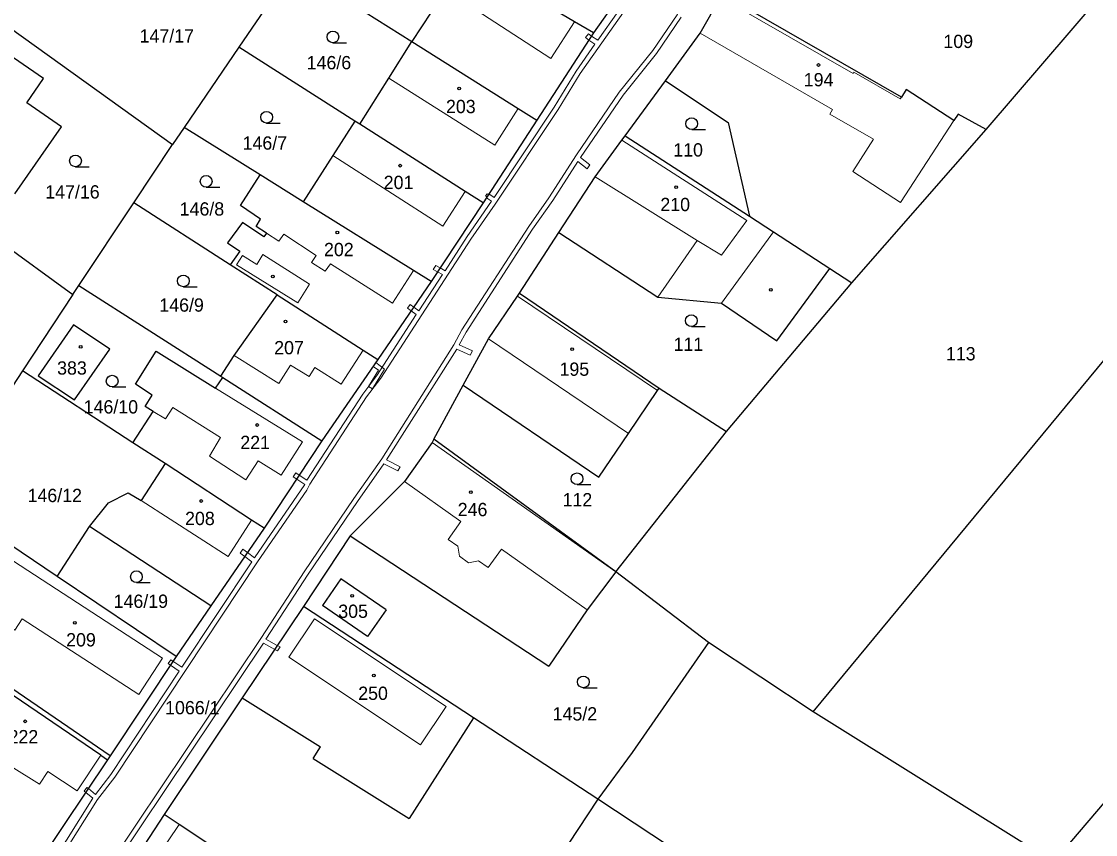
# Model space of a CAD drawing. Extents: x -694609 to -690140, y -1033292 to -1029794.
# Drawn here: x -692824.6 to -692687.4, y -1031527.4 to -1031423.4 of the extents above; entities that cross this region are included whole.
import ezdxf
from ezdxf.enums import TextEntityAlignment as Align

# ---------------------------------------------------------------- set-up
doc = ezdxf.new("R2010")
doc.units = 0
doc.header["$LTSCALE"] = 0.68
for name, color, linetype, lineweight in [('1', 7, 'Continuous', 25), ('13', 7, 'Continuous', 13), ('3', 7, 'Continuous', 25), ('4', 7, 'Continuous', 13), ('5', 7, 'Continuous', 25)]:
    doc.layers.add(name, color=color, linetype=linetype, lineweight=lineweight)
doc.layers.add('2', color=7, linetype='Continuous')

msp = doc.modelspace()

# ---------------------------------------------------------------- linework, layer by layer
at = {"layer": '1'}
for p, q in [((-692743.74, -1031413.72), (-692751.52, -1031424.89)), ((-692753.94, -1031423.46), (-692767.77, -1031415.32)), ((-692789.88, -1031416.45), (-692796.87, -1031426.72)), ((-692789.88, -1031416.45), (-692774.74, -1031425.99)), ((-692701.34, -1031437.24), (-692684.27, -1031417.34)), ((-692832.99, -1031419.3), (-692805.34, -1031439.18)), ((-692770.44, -1031419.41), (-692774.74, -1031425.99)), ((-692712.18, -1031433.11), (-692734.45, -1031420.29)), ((-692751.52, -1031424.89), (-692753.94, -1031423.46)), ((-692751.52, -1031424.89), (-692758.78, -1031436.05)), ((-692742.33, -1031431.01), (-692737.89, -1031424.94)), ((-692821.85, -1031430.74), (-692827.61, -1031426.76)), ((-692796.87, -1031426.72), (-692803.86, -1031437)), ((-692782.03, -1031436.18), (-692796.87, -1031426.72)), ((-692777.68, -1031430.66), (-692774.74, -1031425.99)), ((-692774.74, -1031425.99), (-692761.15, -1031434.55)), ((-692823.98, -1031433.82), (-692821.85, -1031430.74)), ((-692781.41, -1031436.58), (-692777.68, -1031430.66)), ((-692747.5, -1031438.07), (-692742.33, -1031431.01)), ((-692742.33, -1031431.01), (-692734.34, -1031436.36)), ((-692819.54, -1031436.89), (-692823.98, -1031433.82)), ((-692761.15, -1031434.55), (-692758.78, -1031436.05)), ((-692782.03, -1031436.18), (-692784.85, -1031440.58)), ((-692781.41, -1031436.58), (-692782.03, -1031436.18)), ((-692767.95, -1031445.16), (-692781.41, -1031436.58)), ((-692758.78, -1031436.05), (-692765.64, -1031446.63)), ((-692734.34, -1031436.36), (-692731.59, -1031448.35)), ((-692723.47, -1031511.71), (-692660.69, -1031435.82)), ((-692846.51, -1031437.82), (-692818.08, -1031458.33)), ((-692825.49, -1031445.49), (-692819.54, -1031436.89)), ((-692803.86, -1031437), (-692805.34, -1031439.18)), ((-692794.14, -1031443.05), (-692803.86, -1031437)), ((-692747.9, -1031438.62), (-692747.5, -1031438.07)), ((-692747.5, -1031438.07), (-692731.59, -1031448.35)), ((-692718.5, -1031456.87), (-692701.34, -1031437.24)), ((-692810.29, -1031446.62), (-692805.34, -1031439.18)), ((-692784.85, -1031440.58), (-692788.63, -1031446.48)), ((-692796.67, -1031446.97), (-692794.14, -1031443.05)), ((-692788.63, -1031446.48), (-692794.14, -1031443.05)), ((-692765.64, -1031446.63), (-692767.95, -1031445.16)), ((-692817.33, -1031457.2), (-692810.29, -1031446.62)), ((-692797.96, -1031454.55), (-692810.29, -1031446.62)), ((-692794.1, -1031448.71), (-692796.67, -1031446.97)), ((-692774.52, -1031455.26), (-692788.63, -1031446.48)), ((-692765.64, -1031446.63), (-692772.26, -1031456.67)), ((-692796.41, -1031449.12), (-692798.33, -1031451.74)), ((-692793.65, -1031450.98), (-692796.41, -1031449.12)), ((-692794.66, -1031449.64), (-692794.1, -1031448.71)), ((-692731.59, -1031448.35), (-692728.54, -1031450.33)), ((-692793.33, -1031450.5), (-692794.66, -1031449.64)), ((-692793.33, -1031450.5), (-692793.65, -1031450.98)), ((-692728.54, -1031450.33), (-692721.33, -1031455.03)), ((-692798.33, -1031451.74), (-692796.75, -1031452.81)), ((-692796.75, -1031452.81), (-692797.96, -1031454.55)), ((-692791.95, -1031458.41), (-692797.96, -1031454.55)), ((-692692.71, -1031530.91), (-692627.47, -1031454.27)), ((-692772.26, -1031456.67), (-692774.52, -1031455.26)), ((-692728.11, -1031464.28), (-692721.33, -1031455.03)), ((-692721.33, -1031455.03), (-692718.5, -1031456.87)), ((-692818.08, -1031458.33), (-692817.33, -1031457.2)), ((-692817.33, -1031457.2), (-692799.18, -1031468.8)), ((-692772.26, -1031456.67), (-692779.09, -1031466.68)), ((-692734.52, -1031475.87), (-692718.5, -1031456.87)), ((-692818.08, -1031458.33), (-692824.52, -1031468.13)), ((-692797.46, -1031466.14), (-692791.95, -1031458.41)), ((-692791.95, -1031458.41), (-692780.96, -1031465.48)), ((-692761.24, -1031458.54), (-692761, -1031458.16)), ((-692761, -1031458.16), (-692743.13, -1031470.31)), ((-692743.3, -1031458.68), (-692735.18, -1031459.46)), ((-692735.18, -1031459.46), (-692728.11, -1031464.28)), ((-692817.98, -1031462.22), (-692822.5, -1031468.73)), ((-692813.36, -1031465.34), (-692817.98, -1031462.22)), ((-692817.88, -1031471.82), (-692813.36, -1031465.34)), ((-692810.08, -1031469.81), (-692807.42, -1031465.59)), ((-692807.42, -1031465.59), (-692799.83, -1031470.31)), ((-692780.96, -1031465.48), (-692779.09, -1031466.68)), ((-692799.18, -1031468.8), (-692797.46, -1031466.14)), ((-692779.09, -1031466.68), (-692786.24, -1031477.07)), ((-692824.52, -1031468.13), (-692830.61, -1031477.39)), ((-692810.41, -1031477.3), (-692824.52, -1031468.13)), ((-692822.5, -1031468.73), (-692817.88, -1031471.82)), ((-692799.83, -1031470.31), (-692798.93, -1031468.96)), ((-692799.18, -1031468.8), (-692798.93, -1031468.96)), ((-692798.93, -1031468.96), (-692786.24, -1031477.07)), ((-692807.94, -1031471.2), (-692810.08, -1031469.81)), ((-692771.94, -1031476.85), (-692768.18, -1031469.96)), ((-692768.18, -1031469.96), (-692750.83, -1031481.7)), ((-692747.05, -1031476.11), (-692743.35, -1031470.64)), ((-692743.35, -1031470.64), (-692743.13, -1031470.31)), ((-692743.13, -1031470.31), (-692734.52, -1031475.87)), ((-692808.83, -1031472.66), (-692807.94, -1031471.2)), ((-692810.41, -1031477.3), (-692807.8, -1031473.29)), ((-692807.8, -1031473.29), (-692808.83, -1031472.66)), ((-692750.83, -1031481.7), (-692747.05, -1031476.11)), ((-692748.67, -1031493.81), (-692734.52, -1031475.87)), ((-692806.3, -1031479.98), (-692810.41, -1031477.3)), ((-692786.24, -1031477.07), (-692793.62, -1031488.22)), ((-692772.17, -1031477.28), (-692775.69, -1031482.26)), ((-692771.94, -1031476.85), (-692772.17, -1031477.28)), ((-692748.67, -1031493.81), (-692771.94, -1031476.85)), ((-692806.3, -1031479.98), (-692809.33, -1031484.69)), ((-692795.24, -1031487.22), (-692806.3, -1031479.98)), ((-692775.69, -1031482.26), (-692782.63, -1031489.23)), ((-692820.1, -1031494.39), (-692835.25, -1031484.19)), ((-692813.51, -1031484.98), (-692811.03, -1031483.73)), ((-692811.03, -1031483.73), (-692809.33, -1031484.69)), ((-692815.93, -1031488.02), (-692813.51, -1031484.98)), ((-692793.62, -1031488.22), (-692795.24, -1031487.22)), ((-692820.1, -1031494.39), (-692815.93, -1031488.02)), ((-692800.44, -1031498.16), (-692815.93, -1031488.02)), ((-692793.62, -1031488.22), (-692800.44, -1031498.16)), ((-692782.63, -1031489.23), (-692788.61, -1031498.23)), ((-692782.63, -1031489.23), (-692757.26, -1031505.86)), ((-692804.88, -1031504.64), (-692820.1, -1031494.39)), ((-692748.67, -1031493.81), (-692752.33, -1031498.69)), ((-692736.84, -1031502.87), (-692748.67, -1031493.81)), ((-692783.83, -1031494.7), (-692786.18, -1031498.12)), ((-692778.05, -1031498.67), (-692783.83, -1031494.7)), ((-692800.44, -1031498.16), (-692804.88, -1031504.64)), ((-692788.61, -1031498.23), (-692796.44, -1031509.94)), ((-692766.86, -1031512.47), (-692788.61, -1031498.23)), ((-692780.4, -1031502.09), (-692786.18, -1031498.12)), ((-692778.05, -1031498.67), (-692780.4, -1031502.09)), ((-692752.33, -1031498.69), (-692757.26, -1031505.86)), ((-692736.84, -1031502.87), (-692746.58, -1031516.93)), ((-692723.47, -1031511.71), (-692736.84, -1031502.87)), ((-692814.52, -1031517.26), (-692833.22, -1031504.54)), ((-692804.88, -1031504.64), (-692813.29, -1031517.36)), ((-692813.29, -1031517.36), (-692827.38, -1031507.7)), ((-692796.44, -1031509.94), (-692806.41, -1031524.86)), ((-692796.44, -1031509.94), (-692786.44, -1031516.19)), ((-692692.71, -1031530.91), (-692723.47, -1031511.71)), ((-692766.86, -1031512.47), (-692775.09, -1031525.37)), ((-692750.99, -1031522.87), (-692766.86, -1031512.47)), ((-692787.37, -1031517.68), (-692786.44, -1031516.19)), ((-692814.52, -1031517.26), (-692813.63, -1031517.87)), ((-692813.29, -1031517.36), (-692813.63, -1031517.87)), ((-692787.37, -1031517.68), (-692775.09, -1031525.37)), ((-692746.58, -1031516.93), (-692750.99, -1031522.87)), ((-692813.63, -1031517.87), (-692824.08, -1031533.37)), ((-692750.99, -1031522.87), (-692768.7, -1031549.76)), ((-692678.79, -1031570.47), (-692750.99, -1031522.87)), ((-692796.91, -1031531.13), (-692804.51, -1031526.12))]:
    msp.add_line(p, q, dxfattribs=at)
for points in [[(-692737.89, -1031424.94), (-692735.3, -1031420.32), (-692734.72, -1031420.66)], [(-692705.48, -1031436.11), (-692711.56, -1031432.15), (-692712.18, -1031433.11)], [(-692701.34, -1031437.24), (-692704.93, -1031435.27), (-692705.48, -1031436.11)], [(-692755.95, -1031450.41), (-692751.31, -1031443.28), (-692747.9, -1031438.62)], [(-692761, -1031458.16), (-692755.95, -1031450.41), (-692743.3, -1031458.68)], [(-692768.18, -1031469.96), (-692764.94, -1031464), (-692761.24, -1031458.54)], [(-692804.51, -1031526.12), (-692806.41, -1031524.86), (-692816.15, -1031539.83)]]:
    msp.add_lwpolyline(points, dxfattribs=at)
at = {"layer": '13'}
for points in [[(-692821.78, -1031533.86), (-692814.94, -1031522.92), (-692812.73, -1031520.08), (-692794.48, -1031492.55), (-692788.19, -1031483.36), (-692787.79, -1031482.62), (-692780.53, -1031471.44), (-692778.71, -1031469.03), (-692767.21, -1031451.27), (-692764.08, -1031446.79), (-692756.04, -1031434.68), (-692753.23, -1031430.1), (-692736.34, -1031406.09), (-692736.18, -1031405.56), (-692732.41, -1031400.24), (-692726.28, -1031399.91), (-692722.14, -1031396.02), (-692720.43, -1031393.92), (-692719.16, -1031392.37), (-692711.07, -1031383.61), (-692701.14, -1031373.4), (-692697.25, -1031376.64), (-692705.94, -1031386.76)], [(-692731.48, -1031411.34), (-692737.54, -1031417.26), (-692738.96, -1031419.23), (-692740.83, -1031422.56), (-692743.96, -1031427.15), (-692748.24, -1031432.48), (-692753.7, -1031440.49), (-692757.22, -1031445.99), (-692759.8, -1031449.66), (-692768.34, -1031462.88), (-692769.39, -1031464.78), (-692778.6, -1031479.36), (-692782.17, -1031484.44), (-692788.53, -1031493.82), (-692793.95, -1031502.2), (-692813.14, -1031530.87)], [(-692743.18, -1031414.8), (-692750.99, -1031425.83), (-692751.78, -1031425.29), (-692752.11, -1031425.8), (-692751.34, -1031426.33), (-692753.75, -1031429.79), (-692756.55, -1031434.37), (-692764.24, -1031445.94), (-692764.9, -1031445.48), (-692765.22, -1031445.98), (-692764.57, -1031446.43), (-692767.7, -1031450.92), (-692770.49, -1031455.3), (-692771.13, -1031454.95), (-692771.46, -1031455.46), (-692770.82, -1031455.8), (-692773.85, -1031460.44), (-692774.5, -1031459.95), (-692774.84, -1031460.45), (-692774.19, -1031460.92), (-692779.21, -1031468.7), (-692781.03, -1031471.1), (-692788.17, -1031482.1), (-692789.14, -1031481.45), (-692789.47, -1031481.95), (-692788.43, -1031482.65), (-692794.85, -1031492.03), (-692795.77, -1031491.36), (-692796.11, -1031491.85), (-692795.19, -1031492.52), (-692804.14, -1031506), (-692805.28, -1031505.25), (-692805.61, -1031505.74), (-692804.47, -1031506.5), (-692813.22, -1031519.73), (-692815.19, -1031522.27), (-692816.1, -1031521.54), (-692816.43, -1031522.03), (-692815.54, -1031522.77), (-692822.27, -1031533.51)], [(-692812.54, -1031531.06), (-692793.72, -1031502.94), (-692792.28, -1031503.73), (-692791.95, -1031503.23), (-692793.4, -1031502.44), (-692788, -1031494.11), (-692781.7, -1031484.81), (-692778.32, -1031480.01), (-692776.56, -1031480.89), (-692776.23, -1031480.37), (-692778, -1031479.51), (-692769.01, -1031465.32), (-692767.3, -1031466.09), (-692766.99, -1031465.57), (-692768.71, -1031464.8), (-692767.81, -1031463.18), (-692759.31, -1031450.01), (-692756.72, -1031446.31), (-692753.53, -1031441.32), (-692752.32, -1031442.28), (-692752, -1031441.76), (-692753.19, -1031440.82), (-692747.76, -1031432.84), (-692743.48, -1031427.51), (-692740.31, -1031422.87)]]:
    msp.add_lwpolyline(points, dxfattribs=at)
for points in [[(-692752.54, -1031425.5), (-692752.11, -1031425.8), (-692751.78, -1031425.29), (-692752.18, -1031425.01)], [(-692765.14, -1031445.47), (-692765.32, -1031445.74), (-692765.14, -1031445.86), (-692764.96, -1031445.59)], [(-692771.69, -1031454.64), (-692772.01, -1031455.16), (-692771.46, -1031455.46), (-692771.13, -1031454.95)], [(-692775.32, -1031460.09), (-692774.84, -1031460.45), (-692774.5, -1031459.95), (-692774.96, -1031459.61)], [(-692779.34, -1031467.04), (-692779.68, -1031467.54), (-692779.03, -1031468.03), (-692780.3, -1031470.12), (-692779.79, -1031470.43), (-692778.23, -1031467.89)], [(-692789.57, -1031481.16), (-692789.92, -1031481.65), (-692789.47, -1031481.95), (-692789.14, -1031481.45)], [(-692796.11, -1031491.85), (-692795.77, -1031491.36), (-692796.36, -1031490.93), (-692796.71, -1031491.42)], [(-692791.95, -1031503.23), (-692792.28, -1031503.73), (-692791.93, -1031503.92), (-692791.6, -1031503.42)], [(-692805.61, -1031505.74), (-692805.28, -1031505.25), (-692805.56, -1031505.06), (-692805.9, -1031505.54)], [(-692816.62, -1031521.88), (-692816.43, -1031522.03), (-692816.1, -1031521.54), (-692816.28, -1031521.39)]]:
    msp.add_lwpolyline(points, close=True, dxfattribs=at)
at = {"layer": '3'}
for p, q in [((-692784.843, -1031426.15), (-692783.093, -1031426.15)), ((-692793.313, -1031436.43), (-692791.563, -1031436.43)), ((-692738.983, -1031437.25), (-692737.233, -1031437.25)), ((-692817.743, -1031442.01), (-692815.993, -1031442.01)), ((-692801.043, -1031444.63), (-692799.293, -1031444.63)), ((-692803.953, -1031457.36), (-692802.203, -1031457.36)), ((-692739.023, -1031462.44), (-692737.273, -1031462.44)), ((-692813.053, -1031470.17), (-692811.303, -1031470.17)), ((-692753.633, -1031482.66), (-692751.883, -1031482.66)), ((-692809.953, -1031495.19), (-692808.203, -1031495.19)), ((-692752.833, -1031508.64), (-692751.083, -1031508.64))]:
    msp.add_line(p, q, dxfattribs=at)
for centre in [(-692784.8429, -1031425.3998), (-692793.3129, -1031435.6798), (-692738.9829, -1031436.4998), (-692817.7429, -1031441.2598), (-692801.0429, -1031443.8798), (-692803.9529, -1031456.6098), (-692739.0229, -1031461.6898), (-692813.0529, -1031469.4198), (-692753.6329, -1031481.9098), (-692809.9529, -1031494.4398), (-692752.8329, -1031507.8898)]:
    msp.add_circle(centre, 0.75, dxfattribs=at)
at = {"layer": '4'}
for p, q in [((-692770.44, -1031419.41), (-692757, -1031428.16)), ((-692753.94, -1031423.46), (-692757, -1031428.16)), ((-692737.89, -1031424.94), (-692720.99, -1031434.67)), ((-692777.68, -1031430.66), (-692764.15, -1031439.26)), ((-692761.15, -1031434.55), (-692764.15, -1031439.26)), ((-692721.34, -1031435.27), (-692720.99, -1031434.67)), ((-692715.73, -1031438.5), (-692721.34, -1031435.27)), ((-692705.48, -1031436.11), (-692712.31, -1031446.58)), ((-692747.9, -1031438.62), (-692731.94, -1031448.89)), ((-692718.38, -1031442.62), (-692715.73, -1031438.5)), ((-692784.85, -1031440.58), (-692770.79, -1031449.59)), ((-692751.31, -1031443.28), (-692738.26, -1031451.44)), ((-692718.38, -1031442.62), (-692712.31, -1031446.58)), ((-692767.95, -1031445.16), (-692770.79, -1031449.59)), ((-692731.94, -1031448.89), (-692735.19, -1031453.32)), ((-692791.73, -1031451.54), (-692793.33, -1031450.5)), ((-692735.18, -1031459.46), (-692728.54, -1031450.33)), ((-692791.13, -1031450.62), (-692791.73, -1031451.54)), ((-692786.96, -1031453.35), (-692791.13, -1031450.62)), ((-692793.81, -1031453.25), (-692794.56, -1031454.51)), ((-692787.82, -1031457.04), (-692793.81, -1031453.25)), ((-692796.4, -1031453.34), (-692797.18, -1031454.54)), ((-692797.18, -1031454.54), (-692789.32, -1031459.4)), ((-692794.56, -1031454.51), (-692796.4, -1031453.34)), ((-692787.57, -1031454.27), (-692786.96, -1031453.35)), ((-692785.82, -1031455.36), (-692787.57, -1031454.27)), ((-692785.16, -1031454.41), (-692785.82, -1031455.36)), ((-692777.22, -1031459.45), (-692785.16, -1031454.41)), ((-692774.52, -1031455.26), (-692777.22, -1031459.45)), ((-692789.32, -1031459.4), (-692787.82, -1031457.04)), ((-692761.24, -1031458.54), (-692743.35, -1031470.64)), ((-692764.94, -1031464), (-692747.05, -1031476.11)), ((-692790.26, -1031467.37), (-692787.87, -1031468.84)), ((-692787.87, -1031468.84), (-692787.16, -1031467.7)), ((-692799.83, -1031470.31), (-692788.72, -1031477.21)), ((-692807.8, -1031473.29), (-692806.22, -1031474.26)), ((-692805.31, -1031472.79), (-692806.22, -1031474.26)), ((-692799.19, -1031476.64), (-692805.31, -1031472.79)), ((-692800.62, -1031479.01), (-692799.19, -1031476.64)), ((-692788.72, -1031477.21), (-692791.45, -1031481.46)), ((-692748.67, -1031493.81), (-692772.17, -1031477.28)), ((-692795.95, -1031482.03), (-692800.62, -1031479.01)), ((-692794.38, -1031479.64), (-692795.95, -1031482.03)), ((-692791.45, -1031481.46), (-692794.38, -1031479.64)), ((-692809.33, -1031484.69), (-692798.21, -1031491.84)), ((-692795.24, -1031487.22), (-692798.21, -1031491.84)), ((-692825.66, -1031492.47), (-692806.62, -1031504.84)), ((-692787.18, -1031499.81), (-692790.46, -1031504.72)), ((-692770.38, -1031511.03), (-692787.18, -1031499.81)), ((-692806.62, -1031504.84), (-692809.66, -1031509.52)), ((-692773.66, -1031515.94), (-692790.46, -1031504.72)), ((-692770.38, -1031511.03), (-692773.66, -1031515.94)), ((-692814.52, -1031517.26), (-692817.53, -1031521.82)), ((-692825.95, -1031518.71), (-692822.35, -1031520.99)), ((-692822.35, -1031520.99), (-692821.27, -1031519.35)), ((-692821.27, -1031519.35), (-692817.53, -1031521.82)), ((-692804.51, -1031526.12), (-692811.49, -1031536.48))]:
    msp.add_line(p, q, dxfattribs=at)
for points in [[(-692734.72, -1031420.66), (-692718.36, -1031430.08), (-692718.26, -1031429.9), (-692712.32, -1031433.32), (-692712.18, -1031433.11)], [(-692743.3, -1031458.68), (-692738.26, -1031451.44), (-692735.19, -1031453.32)], [(-692787.16, -1031467.7), (-692783.79, -1031469.83), (-692780.96, -1031465.48)], [(-692797.46, -1031466.14), (-692791.75, -1031469.72), (-692790.26, -1031467.37)], [(-692775.69, -1031482.26), (-692768.47, -1031487.36), (-692770.11, -1031489.67), (-692768.88, -1031490.53), (-692768.65, -1031491.8), (-692767.49, -1031492.65), (-692766.21, -1031492.42), (-692764.99, -1031493.27), (-692763.3, -1031490.93), (-692752.33, -1031498.69)], [(-692829.67, -1031498.53), (-692825.5, -1031501.29), (-692824.56, -1031499.84), (-692809.66, -1031509.52)]]:
    msp.add_lwpolyline(points, dxfattribs=at)
at = {"layer": '5'}
for centre in [(-692722.7668, -1031428.9992), (-692768.7168, -1031431.9892), (-692776.2368, -1031441.8692), (-692740.9768, -1031444.6292), (-692784.2768, -1031450.4092), (-692792.5068, -1031456.0392), (-692728.8668, -1031457.7392), (-692790.8968, -1031461.8092), (-692817.0768, -1031465.0292), (-692754.2668, -1031465.3492), (-692794.5068, -1031475.0392), (-692767.2168, -1031483.6392), (-692801.6768, -1031484.7592), (-692782.3668, -1031496.8792), (-692817.8368, -1031500.3392), (-692779.6068, -1031507.0792), (-692824.1668, -1031512.9292)]:
    msp.add_circle(centre, 0.175, dxfattribs=at)

# ---------------------------------------------------------------- texts
at = {"layer": '2'}
for s, p in [('147/17', (-692806.07, -1031426.125)), ('109', (-692704.909, -1031426.825)), ('146/6', (-692785.35, -1031429.545)), ('194', (-692722.759, -1031431.725)), ('203', (-692768.489, -1031435.155)), ('146/7', (-692793.54, -1031439.825)), ('110', (-692739.439, -1031440.705)), ('201', (-692776.449, -1031444.865)), ('147/16', (-692818.13, -1031446.075)), ('210', (-692741.089, -1031447.685)), ('146/8', (-692801.58, -1031448.255)), ('202', (-692784.079, -1031453.445)), ('146/9', (-692804.18, -1031460.545)), ('111', (-692739.399, -1031465.565)), ('207', (-692790.449, -1031465.995)), ('113', (-692704.589, -1031466.775)), ('195', (-692753.979, -1031468.745)), ('146/10', (-692813.22, -1031473.565)), ('221', (-692794.779, -1031478.115)), ('146/12', (-692820.39, -1031484.895)), ('112', (-692753.589, -1031485.445)), ('208', (-692801.839, -1031487.835)), ('246', (-692766.989, -1031486.695)), ('146/19', (-692809.39, -1031498.425)), ('305', (-692782.259, -1031499.705)), ('209', (-692817.039, -1031503.355)), ('250', (-692779.709, -1031510.195)), ('1066/1', (-692802.81, -1031512.035)), ('145/2', (-692753.91, -1031512.825)), ('222', (-692824.399, -1031515.745))]:
    msp.add_text(s, height=1.7, dxfattribs=at).set_placement(p, align=Align.CENTER)
msp.add_text('383', height=1.7, dxfattribs=at).set_placement((-692820.09, -1031468.595))

doc.saveas('drawing.dxf')
